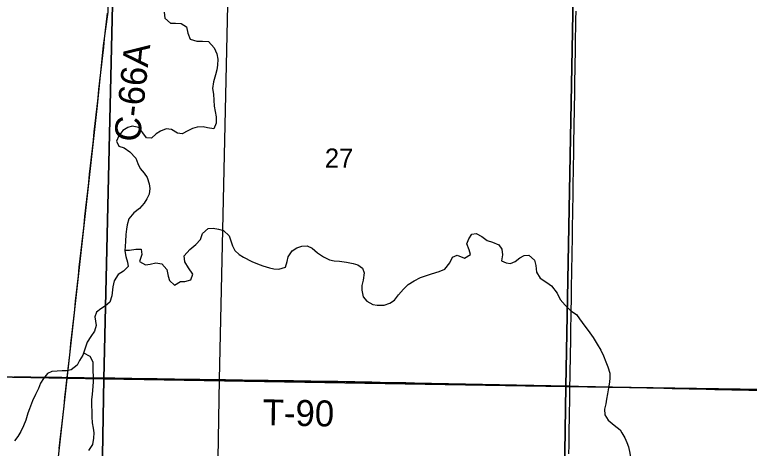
# Model space of a CAD drawing. Extents: x -11.1 to 34, y -3.9 to 22.
# Drawn here: x 4.199 to 5.806, y 19.137 to 20.086 of the extents above; entities that cross this region are included whole.
import ezdxf

# ---------------------------------------------------------------- set-up
doc = ezdxf.new("R2010")
doc.units = 0
for name, color, linetype in [('GM_X_Corporation', 7, 'Continuous'), ('GM_X_County_Road', 7, 'Continuous'), ('GM_X_County_Road_Text', 7, 'Continuous'), ('GM_X_Minor_River', 7, 'Continuous'), ('GM_X_Rail_Line', 7, 'Continuous'), ('GM_X_Section_Text', 7, 'Continuous'), ('GM_X_State_Route', 7, 'Continuous'), ('GM_X_Township_Road', 7, 'Continuous'), ('GM_X_Township_Road_Text', 7, 'Continuous')]:
    doc.layers.add(name, color=color, linetype=linetype)

msp = doc.modelspace()

# ---------------------------------------------------------------- linework, layer by layer
at = {"layer": 'GM_X_Corporation'}
for points in [[(4.4169, 20.2967), (4.3941, 19.2891), (3.3936, 19.3072), (3.4122, 20.3123)], [(4.4169, 20.2967), (5.4232, 20.283), (5.4044, 19.2723), (4.3941, 19.2891)], [(5.4232, 20.283), (6.4249, 20.2637), (6.4054, 19.2568), (5.4044, 19.2723)], [(4.3941, 19.2891), (4.3765, 18.281), (3.3877, 18.2966), (3.3764, 18.2972), (3.3936, 19.3072)], [(4.3941, 19.2891), (5.4044, 19.2723), (5.3892, 18.2641), (4.3966, 18.2798), (4.3765, 18.281)], [(5.4044, 19.2723), (6.4054, 19.2568), (6.3851, 18.2506), (6.3791, 18.2511), (5.3892, 18.2641)]]:
    msp.add_lwpolyline(points, close=True, dxfattribs=at)
at = {"layer": 'GM_X_County_Road'}
for points in [[(4.2964, 19.1366), (4.2985, 19.1552), (4.3005, 19.1737), (4.3026, 19.1922), (4.3046, 19.2107), (4.3067, 19.2293), (4.3087, 19.2478), (4.3108, 19.2663), (4.3122, 19.2793), (4.3137, 19.2922), (4.3157, 19.3107), (4.3177, 19.3292), (4.3198, 19.3478), (4.3218, 19.3663), (4.3239, 19.3848), (4.3259, 19.4033), (4.328, 19.4219), (4.33, 19.4404), (4.3321, 19.4589), (4.3341, 19.4775), (4.3361, 19.496), (4.3382, 19.5145), (4.3402, 19.533), (4.3423, 19.5516), (4.3443, 19.5701), (4.3464, 19.5886), (4.3484, 19.6072), (4.3505, 19.6257), (4.3525, 19.6442), (4.3546, 19.6628), (4.3566, 19.6813), (4.3587, 19.6998), (4.3607, 19.7183), (4.3628, 19.7369), (4.3648, 19.7554), (4.3669, 19.7739), (4.3689, 19.7925), (4.371, 19.811), (4.373, 19.8295), (4.3751, 19.848), (4.3771, 19.8666), (4.3791, 19.8851), (4.3812, 19.9036), (4.3832, 19.9222), (4.3853, 19.9407), (4.3873, 19.9592), (4.3894, 19.9777), (4.3914, 19.9963), (4.3935, 20.0148), (4.3955, 20.0333), (4.3976, 20.0519), (4.3996, 20.0704), (4.4017, 20.0889)], [(4.1966, 19.2936), (4.2153, 19.2934), (4.2339, 19.2931), (4.2526, 19.2929), (4.2712, 19.2927), (4.2898, 19.2925), (4.3017, 19.2923), (4.3137, 19.2922)]]:
    msp.add_lwpolyline(points, dxfattribs=at)
at = {"layer": 'GM_X_Minor_River'}
for points in [[(4.5255, 20.0914), (4.5275, 20.0784), (4.5397, 20.0671), (4.5503, 20.0669), (4.5632, 20.0666), (4.5748, 20.0595), (4.5772, 20.045), (4.5829, 20.0319), (4.5973, 20.0278), (4.6098, 20.0279), (4.6227, 20.0268), (4.6349, 20.0129), (4.641, 20.0002), (4.643, 19.9884), (4.6427, 19.9755), (4.641, 19.9653), (4.6381, 19.9539), (4.6339, 19.9388), (4.6313, 19.9241), (4.6337, 19.9115), (4.6342, 19.8986), (4.635, 19.8853), (4.637, 19.8738), (4.6394, 19.8624), (4.6395, 19.8483), (4.6346, 19.8363), (4.6206, 19.8381), (4.6108, 19.8406), (4.5979, 19.8398), (4.5876, 19.837), (4.5776, 19.8315), (4.5654, 19.8254), (4.5548, 19.8267), (4.5417, 19.8343), (4.5303, 19.8357), (4.5181, 19.8306), (4.5084, 19.8248), (4.498, 19.8159), (4.487, 19.8162), (4.4789, 19.827), (4.4701, 19.8386), (4.4561, 19.8416), (4.4465, 19.8387), (4.4354, 19.8322)], [(4.4354, 19.8322), (4.4264, 19.821), (4.4216, 19.8093), (4.4267, 19.7982), (4.4383, 19.7941), (4.4503, 19.7859), (4.4636, 19.7719), (4.4679, 19.76), (4.473, 19.7493), (4.4818, 19.7392), (4.4888, 19.7295), (4.4931, 19.7158), (4.4947, 19.7051), (4.4933, 19.6933), (4.4881, 19.6828), (4.4822, 19.6731), (4.4717, 19.6619), (4.4594, 19.652), (4.4488, 19.6389), (4.4448, 19.6261), (4.4434, 19.6163), (4.442, 19.6045), (4.4409, 19.5894), (4.4403, 19.5791), (4.4397, 19.5693), (4.442, 19.5567), (4.4452, 19.5444), (4.4469, 19.5349), (4.4371, 19.5245), (4.4252, 19.5172), (4.4166, 19.5037), (4.4132, 19.4901), (4.4113, 19.4704), (4.4068, 19.4568), (4.3971, 19.4487), (4.3871, 19.4425), (4.3774, 19.4347), (4.3742, 19.4249), (4.3755, 19.4154), (4.3772, 19.4055), (4.3731, 19.3931), (4.3656, 19.3815), (4.357, 19.3691), (4.3533, 19.3559), (4.3476, 19.3405), (4.3409, 19.3289), (4.3354, 19.3187), (4.3222, 19.3088), (4.3119, 19.3068), (4.3025, 19.3066), (4.2918, 19.3057), (4.2804, 19.3048), (4.2708, 19.3009), (4.2615, 19.2897), (4.2556, 19.2796), (4.2508, 19.2679), (4.2444, 19.2548), (4.2376, 19.2409), (4.2315, 19.2236), (4.2279, 19.2138), (4.223, 19.1987), (4.2182, 19.1863), (4.2126, 19.1739), (4.2059, 19.163), (4.1981, 19.1533)], [(4.4398, 19.5706), (4.4499, 19.5705), (4.4637, 19.5729), (4.4758, 19.573), (4.477, 19.5608), (4.4721, 19.5457), (4.4849, 19.5382), (4.4955, 19.5399), (4.5074, 19.5426), (4.5206, 19.5404), (4.5317, 19.528), (4.5348, 19.5139), (4.5376, 19.5039), (4.5484, 19.4942), (4.5614, 19.5022), (4.5713, 19.502), (4.5843, 19.5055), (4.5887, 19.5179), (4.5788, 19.5315), (4.5711, 19.5449), (4.5695, 19.5579), (4.582, 19.5717), (4.5951, 19.5831), (4.6049, 19.5935), (4.6097, 19.6067), (4.6217, 19.6178), (4.6327, 19.6187), (4.6448, 19.6165), (4.6558, 19.6136), (4.6676, 19.6016), (4.6716, 19.5908), (4.6755, 19.5797), (4.6802, 19.5697), (4.6899, 19.5612), (4.6996, 19.5549), (4.7176, 19.5457), (4.7296, 19.5409), (4.7413, 19.5364), (4.756, 19.5315), (4.7658, 19.5298), (4.7764, 19.5288), (4.7909, 19.5334), (4.795, 19.5458), (4.7971, 19.556), (4.8061, 19.5691), (4.8158, 19.5757), (4.8272, 19.5792), (4.8382, 19.5797), (4.8495, 19.5749), (4.8614, 19.5648), (4.8741, 19.5557), (4.8876, 19.5494), (4.8978, 19.5472), (4.9092, 19.5462), (4.9243, 19.5443), (4.939, 19.5417), (4.9496, 19.5384), (4.9593, 19.531), (4.9632, 19.5206), (4.961, 19.5047), (4.958, 19.493), (4.9578, 19.4832), (4.9613, 19.4687), (4.9694, 19.4586), (4.9821, 19.4518), (4.992, 19.4505), (5.0071, 19.4505), (5.0194, 19.4544), (5.0298, 19.461), (5.038, 19.4729), (5.0493, 19.4852), (5.0594, 19.4956), (5.0725, 19.5037), (5.0863, 19.5109), (5.0977, 19.5145), (5.1103, 19.5184), (5.1272, 19.524), (5.1394, 19.5291), (5.1503, 19.5425), (5.1567, 19.5549), (5.167, 19.5596), (5.1825, 19.5531), (5.1955, 19.5612), (5.1927, 19.5715), (5.1881, 19.5845), (5.1921, 19.5955), (5.1984, 19.6056), (5.208, 19.6069), (5.2203, 19.6005), (5.2323, 19.5915), (5.2443, 19.5882), (5.2575, 19.5822), (5.2641, 19.5725), (5.2661, 19.5603), (5.2639, 19.5475), (5.2736, 19.543), (5.2835, 19.5417), (5.2934, 19.5456), (5.3035, 19.5541), (5.3131, 19.5585), (5.3233, 19.5597)], [(5.3233, 19.5597), (5.3356, 19.5484), (5.3384, 19.537), (5.3403, 19.5221), (5.3484, 19.5094), (5.3626, 19.4996), (5.373, 19.4925), (5.3852, 19.4767), (5.3917, 19.4625), (5.4028, 19.45), (5.415, 19.438), (5.4274, 19.4297), (5.4344, 19.4201), (5.4458, 19.4042), (5.4535, 19.3946), (5.4638, 19.3795), (5.4729, 19.3645), (5.4806, 19.3514), (5.4868, 19.3395), (5.4922, 19.3264), (5.4965, 19.3153), (5.5003, 19.3012), (5.5009, 19.2913), (5.4999, 19.2818), (5.4977, 19.2693), (5.4955, 19.2565), (5.493, 19.2444), (5.4916, 19.2345), (5.4887, 19.2225), (5.4899, 19.2099), (5.4972, 19.1983), (5.5099, 19.1874), (5.5229, 19.1772)], [(4.3495, 19.3457), (4.3631, 19.3386), (4.3697, 19.3263), (4.3696, 19.3081), (4.3704, 19.2929), (4.3706, 19.2822), (4.37, 19.2727), (4.3681, 19.2549), (4.367, 19.2436), (4.3668, 19.2322), (4.3672, 19.2162), (4.3677, 19.2056), (4.3685, 19.1926), (4.3705, 19.1808), (4.3718, 19.1705), (4.3712, 19.1592), (4.369, 19.1455), (4.3603, 19.1321)], [(5.5229, 19.1772), (5.5271, 19.171), (5.5337, 19.1602), (5.5379, 19.1499), (5.5415, 19.1399), (5.5441, 19.1262), (5.5464, 19.1125), (5.5438, 19.1004), (5.5345, 19.0908)]]:
    msp.add_lwpolyline(points, dxfattribs=at)
at = {"layer": 'GM_X_Rail_Line'}
for points in [[(4.8375, 14.1), (4.84, 14.2474), (4.8556, 15.259), (4.8714, 16.2666), (4.8783, 16.7081), (4.896, 17.8593), (4.8941, 17.9315), (4.8895, 17.9844), (4.8767, 18.0419), (4.6837, 18.6752), (4.6608, 18.751), (4.6471, 18.7984), (4.6397, 18.855), (4.6467, 19.2877), (4.6769, 20.631), (4.6804, 20.8229), (4.6818, 20.9)], [(4.6802, 20.8234), (4.6549, 20.7884), (4.6249, 20.7501), (4.5791, 20.6563), (4.5461, 20.6338), (4.4803, 20.5968), (4.4302, 20.5688), (4.4098, 20.5528), (4.3973, 20.5266), (4.3918, 20.4856), (4.3909, 20.4464), (4.3968, 20.2646), (4.4015, 20.1476), (4.4029, 20.091), (4.3921, 20.0182), (4.3791, 19.887), (4.2803, 18.9936), (4.2822, 18.9589), (4.3352, 18.597), (4.3921, 18.288), (4.3976, 18.2496), (4.3933, 17.8598)]]:
    msp.add_lwpolyline(points, dxfattribs=at)
at = {"layer": 'GM_X_State_Route'}
msp.add_lwpolyline([(5.4112, 19.125), (5.4115, 19.1437), (5.4118, 19.1623), (5.412, 19.181), (5.4123, 19.1996), (5.4126, 19.2182), (5.4129, 19.2369), (5.4132, 19.2551), (5.4134, 19.2733), (5.4138, 19.292), (5.4141, 19.3106), (5.4144, 19.3293), (5.4147, 19.3479), (5.415, 19.3665), (5.4153, 19.3852), (5.4156, 19.4038), (5.4159, 19.4225), (5.4162, 19.4411), (5.4165, 19.4598), (5.4168, 19.4784), (5.4171, 19.497), (5.4174, 19.5157), (5.4177, 19.5343), (5.418, 19.553), (5.4183, 19.5716), (5.4186, 19.5902), (5.4189, 19.6089), (5.4192, 19.6275), (5.4195, 19.6462), (5.4198, 19.6648), (5.4201, 19.6834), (5.4204, 19.7021), (5.4207, 19.7207), (5.421, 19.7394), (5.4213, 19.758), (5.4216, 19.7766), (5.4219, 19.7953), (5.4222, 19.8139), (5.4225, 19.8326), (5.4228, 19.8512), (5.4231, 19.8699), (5.4234, 19.8885), (5.4237, 19.9071), (5.424, 19.9258), (5.4243, 19.9444), (5.4246, 19.9631), (5.4249, 19.9817), (5.4252, 20.0003), (5.4255, 20.019), (5.4258, 20.0376), (5.4261, 20.0563), (5.4264, 20.0749), (5.4268, 20.0935)], dxfattribs=at)
at = {"layer": 'GM_X_Township_Road'}
for points in [[(4.3137, 19.2922), (4.3323, 19.2919), (4.3509, 19.2917), (4.3696, 19.2915), (4.3842, 19.2913), (4.3989, 19.2911), (4.4176, 19.2908), (4.4362, 19.2906), (4.4548, 19.2903), (4.4735, 19.29), (4.4921, 19.2897), (4.5108, 19.2895), (4.5294, 19.2892), (4.5481, 19.2889), (4.5667, 19.2886), (4.5853, 19.2883), (4.604, 19.2881), (4.6226, 19.2878), (4.6413, 19.2875), (4.6599, 19.2872), (4.6785, 19.2869), (4.6972, 19.2867), (4.7158, 19.2864), (4.7345, 19.2861), (4.7531, 19.2858), (4.7717, 19.2855), (4.7904, 19.2853), (4.809, 19.285), (4.8277, 19.2847), (4.8463, 19.2844), (4.865, 19.2842), (4.8836, 19.2839), (4.8945, 19.2837), (4.9054, 19.2836), (4.924, 19.2832), (4.9426, 19.2828), (4.9613, 19.2824), (4.9799, 19.2821), (4.9985, 19.2817), (5.0172, 19.2813), (5.0358, 19.281), (5.0544, 19.2806), (5.0731, 19.2802), (5.0917, 19.2798), (5.1103, 19.2795), (5.129, 19.2791), (5.1476, 19.2787), (5.1662, 19.2783), (5.1849, 19.278), (5.2035, 19.2776), (5.2221, 19.2772), (5.2408, 19.2768), (5.2594, 19.2764), (5.2781, 19.2761), (5.2967, 19.2757), (5.3153, 19.2753), (5.334, 19.2749), (5.3526, 19.2746), (5.3712, 19.2742), (5.3899, 19.2738), (5.4017, 19.2736), (5.4134, 19.2733)], [(5.4134, 19.2733), (5.4321, 19.2729), (5.4507, 19.2725), (5.4694, 19.272), (5.488, 19.2716), (5.5066, 19.2712), (5.5253, 19.2707), (5.5439, 19.2703), (5.5625, 19.2699), (5.5812, 19.2694), (5.5998, 19.269), (5.6184, 19.2686), (5.6371, 19.2681), (5.6557, 19.2677), (5.6743, 19.2673), (5.693, 19.2668), (5.7116, 19.2664), (5.7302, 19.2659), (5.7489, 19.2655), (5.7675, 19.2651), (5.7861, 19.2646), (5.8048, 19.2642), (5.8234, 19.2638)]]:
    msp.add_lwpolyline(points, dxfattribs=at)

# ---------------------------------------------------------------- texts
at = {"layer": 'GM_X_County_Road_Text'}
msp.add_text('C-66A', height=0.05682, rotation=83.8207, dxfattribs=at).set_placement((4.4723, 19.8057))
at = {"layer": 'GM_X_Section_Text'}
msp.add_text('27', height=0.04186, rotation=0, dxfattribs=at).set_placement((4.8773, 19.7511))
at = {"layer": 'GM_X_Township_Road_Text'}
msp.add_text('T-90', height=0.05682, rotation=358.939, dxfattribs=at).set_placement((4.7409, 19.1874))

doc.saveas('drawing.dxf')
